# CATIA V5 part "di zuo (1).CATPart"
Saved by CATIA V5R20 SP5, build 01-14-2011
Part number: 创意作品
Bounding box of the stored display mesh (mm): x -60 to 60, y -40 to 40, z 0 to 325
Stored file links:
  E:\姜浩然03.08\创意作品\di zuo (1).CATPart
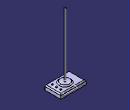
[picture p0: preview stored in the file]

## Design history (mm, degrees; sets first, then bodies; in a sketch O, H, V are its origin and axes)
Body1 (main body)
  Sketch1 on xy-plane, origin (0, 0, 0), H (1, 0, 0), V (0, 1, 0)
    line L1 (60, 40) -> (60, -40)
    line L2 (60, -40) -> (-60, -40)
    line L3 (-60, -40) -> (-60, 40)
    line L4 (-60, 40) -> (60, 40)
    vertical: L1 V, L3 V
    horizontal: L2 H, L4 H
    equidistance: L1 L3 O, L2 L4 O
  Pad1: profile Sketch1, direction (0, 0, 1), length 20
  Sketch2 on end face of Pad1, origin (0, 0, 20), H (1, 0, 0), V (0, 1, 0)
    circle A1 centre (0, 0) radius 22.3607
  Pad2: profile Sketch2, direction (0, 0, 1), length 5
  Fillet1: radius 5, on face of Pad1 from Sketch1.L2; end face of Pad1
Body2
  Sketch3 on end face of Pad2, origin (0, 0, 25), H (1, 0, 0), V (0, 1, 0)
    circle A1 centre (0, 0) radius 5
    point P1 (5, 0)
    radius A1 = 5
    coincidence: A1 P1, P1 H
  Pad3: profile Sketch3, direction (0, 0, 1), length 300
Body3
  Sketch4 on end face of Pad1, origin (0, 0, 20), H (1, 0, 0), V (0, 1, 0)
    circle A1 centre (40, 20) radius 3.5
    circle A2 centre (40, 0) radius 3.5
    point P2 (40, 0)
    point P3 (43.5, 0)
    circle A3 centre (40, -20) radius 3.5
    radius A1 = 3.5
    radius A2 = 3.5
    radius A3 = 3.5
    coincidence: P2 H, A2 P3, P3 H
  Pad4: profile Sketch4, direction (0, 0, 1), length 2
